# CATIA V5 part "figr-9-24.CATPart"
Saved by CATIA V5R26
Part number: Part2
Bounding box of the stored display mesh (mm): x -72 to 72, y -80 to 90, z -20 to 41.296
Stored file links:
  D:\_Deepak\CATIA\CATIA V5-6R2016_Deepak\Resources\Part files\Partfiles\c09_catia_v5_6r2016_prt\figr-9-24.CATPart
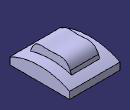
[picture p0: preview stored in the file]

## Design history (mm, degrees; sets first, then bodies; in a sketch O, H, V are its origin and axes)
Body1 (main body)
  Sketch1 on yz-plane, origin (0, 0, 0), H (0, 1, 0), V (0, 0, 1)
    arc A1 centre (5, -170) radius 190.0658 from (-80, 0) to (90, 0) cw
    point P2 (-80, 0)
    point P3 (0, 20)
    line L1 (-80, 0) -> (-80, -20)
    line L2 (-80, -20) -> (90, -20)
    line L3 (90, -20) -> (90, 0)
    coincidence: P2 H, A1 P3, P3 V
    vertical: L1 V, L3 V
    horizontal: L2 H
  Pad1: profile Sketch1, direction (1, 0, 0), length 72, mirrored extent
  Sketch2 on yz-plane, origin (0, 0, 0), H (0, 1, 0), V (0, 0, 1)
    spline S1 through (60, 20) (40, 40) (10, 40) (-10, 40) (-30, 40) (-50, 20)
  Sketch3 on zx-plane, origin (0, 0, 0), H (-1, 0, 0), V (0, 0, 1)
    line L1 (-40, 30) -> (40, 30)
    horizontal: L1 H
  Rib1: profile Sketch2, centre curve Sketch3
